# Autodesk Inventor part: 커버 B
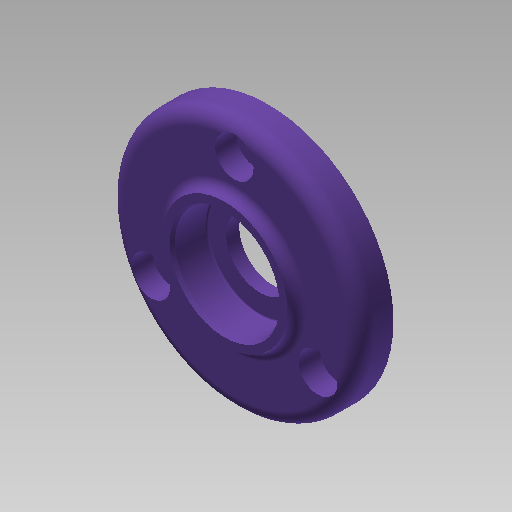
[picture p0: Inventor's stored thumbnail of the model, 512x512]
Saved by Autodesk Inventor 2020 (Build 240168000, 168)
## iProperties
Created: 2020-04
Part Number: 커버 B
Material: 알루미늄 6061
Document SubType Name: Modeling
Designer: mduedu
Density: 2.71 g/cm^3
Mass: 35.0673 g
Surface Area: 63.5388 cm^2
Volume: 12.9399 cm^3
Appearance: 보라색
Author: mduedu
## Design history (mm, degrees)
sketch "스케치1"
  geometry: C1 r 26 at (0, 0); 1 further point
  constraints: 1 centre point, 1 coincident
  dimensions: "d0" = 52 diameter of C1
extrude "돌출1" new body sketch "스케치1" distance "d1" = 7; taper "d2" = 0 deg
sketch "스케치6"
  geometry: C1 r 13 at (0, 0); 1 further point
  constraints: 1 centre point, 1 coincident
  dimensions: "d29" = 26 diameter of C1
extrude "돌출5" join sketch "스케치6" distance "d30" = 2; taper "d31" = 0 deg
fillet "모깎기2" dims "d7" = 3
fillet "모깎기4" dims "d33" = 2
sketch "스케치3" dims "d8" = 40
  geometry: 3 further points
  constraints: 2 vertical alignment, 1 coincident, 2 other
hole "구멍1" sketch "스케치3" at (0, 20) diameter "d9" = 4.5; stored, may be unused: countersink angle "d13" = 90 deg, drill point angle "d15" = 118 deg; dims "d10" = 6, "d11" = 8, "d12" = 4.4, "d14" = 8
sketch "스케치4"
  geometry: C1 r 14 at (0, 0); 1 further point
  constraints: 1 centre point, 1 coincident
  dimensions: "d19" = 28 diameter of C1
extrude "돌출3" join sketch "스케치4" distance "d20" = 4; taper "d21" = 0 deg
sketch "스케치5"
  geometry: C1 r 12 at (0, 0); 1 further point
  constraints: 1 centre point, 1 coincident
  dimensions: "d22" = 24 diameter of C1
extrude "돌출4" cut sketch "스케치5" distance "d23" = 3; taper "d24" = 0 deg
fillet "모깎기3" dims "d25" = 3
chamfer "모따기1" distance "d26" = 0.5; stored, may be unused: second distance "d27" = 2, angle "d28" = 45 deg
sketch "스케치7"
  geometry: 2 further points
  constraints: 1 coincident
hole "구멍2" sketch "스케치7" at (0, 0) diameter "d34" = 14; stored, may be unused: countersink angle "d38" = 90 deg, drill point angle "d40" = 118 deg; dims "d35" = 6, "d36" = 22, "d37" = 7.3, "d39" = 8
fillet "모깎기5" dims "d41" = 0.3
chamfer "모따기2" distance "d42" = 0.7; stored, may be unused: second distance "d43" = 2, angle "d44" = 30 deg
node "솔리드1"
pattern_circular "원형 패턴1" dims angle "d17" = 360 deg
